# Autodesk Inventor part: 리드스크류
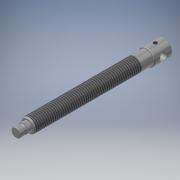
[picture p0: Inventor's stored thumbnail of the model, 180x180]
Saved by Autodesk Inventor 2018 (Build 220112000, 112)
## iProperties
Created: 2019-04
Part Number: 리드스크류
Material: 강철, 연강
Document SubType Name: Modeling
Designer: mduedu
Density: 1 g/cm^3
Appearance: Steel
Author: mduedu
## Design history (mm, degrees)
sketch "스케치1"
  geometry: C1 r 6 at (0, 0); 1 further point
  constraints: 1 centre point, 1 coincident
  dimensions: "d0" = 12 diameter of C1
extrude "돌출1" new body sketch "스케치1" distance "d1" = 100; taper "d2" = 0 deg
sketch "스케치2"
  geometry: C1 r 4 at (0, 0); 1 further point
  constraints: 1 centre point, 1 coincident
  dimensions: "d3" = 8 diameter of C1
extrude "돌출2" join sketch "스케치2" distance "d4" = 10; taper "d5" = 0 deg
sketch "스케치3"
  geometry: C1 r 7 at (0, 0); 1 further point
  constraints: 1 centre point, 1 coincident
  dimensions: "d9" = 14 diameter of C1
extrude "돌출3" join sketch "스케치3" distance "d10" = 15; taper "d11" = 0 deg
feature "스레드1" dims "d12" = 90, "d13" = 0
chamfer "모따기2" distance "d14" = 1; stored, may be unused: second distance "d15" = 2, angle "d16" = 45 deg
chamfer "모따기3" distance "d17" = 0.5; stored, may be unused: second distance "d18" = 2, angle "d19" = 45 deg
chamfer "모따기4" distance "d20" = 0.5; stored, may be unused: second distance "d21" = 2, angle "d22" = 45 deg
sketch "스케치4"
  geometry: L1 (-100, -5)-(-100, 5) reference; L2 (-109.5, 4)-(-109.5, -4) reference; L3 (-109.5, 0)-(-100, 0); C1 r 1.25 at (-105, 4); 1 further point
  constraints: 2 end point, 2 midpoint, 1 centre point
  dimensions: "d23" = 2.5 diameter of C1; "d24" = 5 distance from line of C1.centre L1; "d25" = 4 distance from line of C1.centre L3
revolve "회전1" sketch "스케치4" stored, may be unused: angle "d26" = 90 deg
sketch "스케치5"
  geometry: L1 (0, -6.5)-(0, 6.5) reference; C1 r 3 at (7.5, 0); 2 further points
  constraints: 1 centre point, 1 horizontal alignment, 1 midpoint
  dimensions: "d27" = 6 diameter of C1; "d28" = 7.5 distance from line of C1.centre L1
extrude "돌출4" cut sketch "스케치5" extent not by distance; stored distance "d29" = 15; taper "d30" = 0 deg
node "작업 평면1"
sketch "스케치6"
  geometry: L1 (0, 6.5)-(0, -6.5) reference; 2 further points
  constraints: 1 horizontal alignment
  dimensions: "d31" = 7.5 distance from line of point (-7.5, 0) L1
hole "구멍1" sketch "스케치6" at (-7.5, 0) diameter "d32" = 3.242; stored, may be unused: countersink angle "d36" = 90 deg, drill point angle "d38" = 118 deg; dims "d33" = 6, "d34" = 4, "d35" = 2, "d37" = 8
node "솔리드1"
